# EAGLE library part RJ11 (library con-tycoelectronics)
CORCOM Modular RJ Jacks No Shield Source: www.tycoelectronics.com .. ENG_DS_1654001_1099_RJ_L_0507.pdf
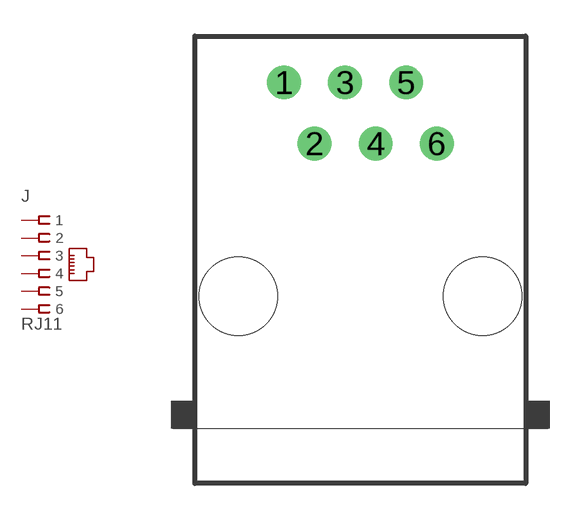
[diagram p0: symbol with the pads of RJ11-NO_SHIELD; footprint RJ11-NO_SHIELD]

Designator prefix J

## RJ11-2L-B (MF: TYCO ELECTRONICS; MPN: RJ11-2L-B; OC_FARNELL: unknown; OC_NEWARK: 83F4463), RJ11-2L-S (MPN: RJ11-2L-S; OC_FARNELL: unknown; OC_NEWARK: 73K3294), RJ11-2X (OC_FARNELL: unknown; OC_NEWARK: unknown), RJ11-4L-B (MF: TYCO ELECTRONICS; MPN: RJ11-4L-B; OC_FARNELL: unknown; OC_NEWARK: 52K3315), RJ11-4L-S (MPN: RJ11-4L-S; OC_FARNELL: unknown; OC_NEWARK: 69K7126), RJ11-4X (MPN: 6609214-3; OC_FARNELL: unknown; OC_NEWARK: 19R7022), RJ11-6L-B (MF: TYCO ELECTRONICS; MPN: RJ11-6L-B; OC_FARNELL: unknown; OC_NEWARK: 52K3613), RJ11-6L-S (MF: TYCO ELECTRONICS; MPN: RJ11-6L-S; OC_FARNELL: 1654827; OC_NEWARK: 50F1358), RJ11-6X (MPN: RJ11-6X; OC_FARNELL: unknown; OC_NEWARK: 16R6089)  [RJ11-NO_SHIELD]
1  1  pas
2  2  pas
3  3  pas
4  4  pas
5  5  pas
6  6  pas

## Footprint RJ11-NO_SHIELD (pad centres in mm)
RJ11 Low Profile No Shield For all RJ11 N and Z Series Models Source: www.tycoelectronics.com .. ENG_DS_1654001_1099_RJ_L_0507.pdf
drill 0.9 pad 1.4 round: 1 -3.175,8.89; 2 -1.905,6.35; 3 -0.635,8.89; 4 0.635,6.35; 5 1.905,8.89; 6 3.175,6.35
hole 3.251 at -5.08,0
hole 3.251 at 5.08,0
